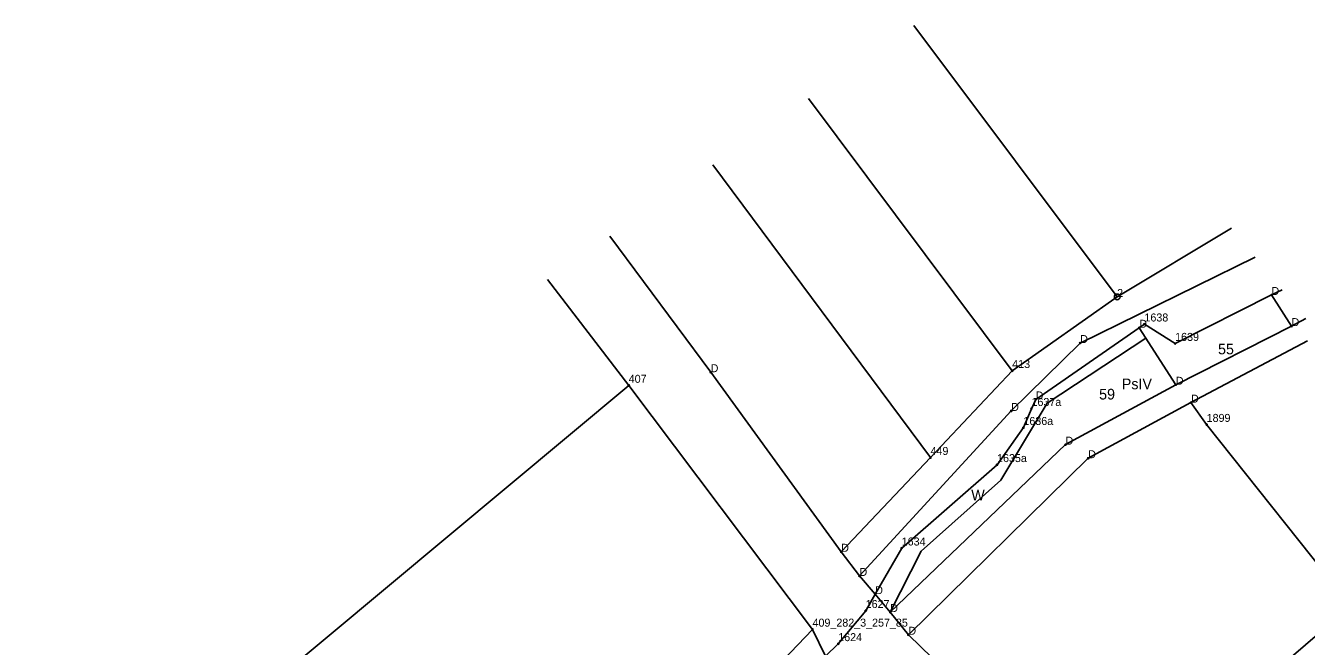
# Model space of a CAD drawing. Extents: x 7467189 to 7469366, y 5491487 to 5492734.
# Drawn here: x 7467205.5 to 7467385.5, y 5492646.7 to 5492734 of the extents above; entities that cross this region are included whole.
import ezdxf

# ---------------------------------------------------------------- set-up
doc = ezdxf.new("R2010")
doc.units = 0
for name, color, linetype in [('202-punkt graniczny', 7, 'Continuous'), ('202-punkt graniczny-Atr103', 7, 'Continuous'), ('203-punkt graniczny', 7, 'Continuous'), ('203-punkt graniczny-Atr103', 7, 'Continuous'), ('209-oznaczenie konturu klasyfikacyjnego', 7, 'Continuous'), ('210-oznaczenie konturu użytku gruntowego', 7, 'Continuous'), ('211-numer działki ewidencyjnej', 7, 'Continuous'), ('217-kontur klasyfikacyjny', 7, 'Continuous'), ('218-kontur użytku gruntowego', 7, 'Continuous'), ('219-działka ewidencyjna', 7, 'Continuous')]:
    doc.layers.add(name, color=color, linetype=linetype)

# ---------------------------------------------------------------- blocks, each defined once
blk = doc.blocks.new('203')
blk.add_circle((0, 0), 0.09)
blk = doc.blocks.new('202')
blk.add_circle((0, 0), 0.4)

msp = doc.modelspace()

# ---------------------------------------------------------------- linework, layer by layer
at = {"layer": '217-kontur klasyfikacyjny'}
for points in [[(7467358.92, 5492695.86), (7467374.98, 5492705.51)], [(7467287.64, 5492704.41), (7467301.8, 5492685.28)], [(7467290.28, 5492683.42), (7467278.88, 5492698.33)], [(7467344.17, 5492685.49), (7467358.92, 5492695.86)], [(7467380.6, 5492696.14), (7467367.07, 5492689.31)], [(7467383.43, 5492691.76), (7467380.6, 5492696.14)], [(7467362.75, 5492692.03), (7467362.03, 5492691.53)], [(7467362.03, 5492691.53), (7467362.95, 5492690.08)], [(7467367.07, 5492689.31), (7467362.75, 5492692.03)], [(7467367.16, 5492683.51), (7467383.43, 5492691.76)], [(7467362.95, 5492690.08), (7467349.1, 5492680.93)], [(7467385.67, 5492689.68), (7467369.29, 5492681)], [(7467332.69, 5492673.27), (7467344.17, 5492685.49)], [(7467301.8, 5492685.28), (7467320.14, 5492660.03)], [(7467316.11, 5492649.12), (7467290.28, 5492683.42)], [(7467351.66, 5492675.09), (7467367.16, 5492683.51)], [(7467349.1, 5492680.93), (7467342.58, 5492670.08)], [(7467369.29, 5492681), (7467354.84, 5492673.18)], [(7467327.03, 5492651.55), (7467351.66, 5492675.09)], [(7467320.14, 5492660.03), (7467332.69, 5492673.27)], [(7467354.84, 5492673.18), (7467329.58, 5492648.36)], [(7467342.58, 5492670.08), (7467331.38, 5492660.13)], [(7467331.38, 5492660.13), (7467327.03, 5492651.55)], [(7467294.41, 5492626.43), (7467316.11, 5492649.12)], [(7467329.58, 5492648.36), (7467374.17, 5492604.99)]]:
    msp.add_lwpolyline(points, dxfattribs=at)
at = {"layer": '218-kontur użytku gruntowego'}
for points in [[(7467358.92, 5492695.86), (7467374.98, 5492705.51)], [(7467287.64, 5492704.41), (7467301.8, 5492685.28)], [(7467378.33, 5492701.44), (7467353.72, 5492689.38)], [(7467290.28, 5492683.42), (7467278.88, 5492698.33)], [(7467382.12, 5492696.86), (7467380.6, 5492696.14)], [(7467344.17, 5492685.49), (7467358.92, 5492695.86)], [(7467380.6, 5492696.14), (7467367.07, 5492689.31)], [(7467383.43, 5492691.76), (7467380.6, 5492696.14)], [(7467383.43, 5492691.76), (7467385.43, 5492692.85)], [(7467362.03, 5492691.53), (7467347.47, 5492681.45)], [(7467362.75, 5492692.03), (7467362.03, 5492691.53)], [(7467362.95, 5492690.08), (7467362.03, 5492691.53)], [(7467367.07, 5492689.31), (7467362.75, 5492692.03)], [(7467367.16, 5492683.51), (7467383.43, 5492691.76)], [(7467353.72, 5492689.38), (7467344.03, 5492679.83)], [(7467349.1, 5492680.93), (7467362.95, 5492690.08)], [(7467385.67, 5492689.68), (7467369.29, 5492681)], [(7467332.69, 5492673.27), (7467344.17, 5492685.49)], [(7467301.8, 5492685.28), (7467320.14, 5492660.03)], [(7467316.11, 5492649.12), (7467290.28, 5492683.42)], [(7467351.66, 5492675.09), (7467367.16, 5492683.51)], [(7467342.58, 5492670.08), (7467349.1, 5492680.93)], [(7467346.88, 5492680.15), (7467345.74, 5492677.48)], [(7467347.47, 5492681.45), (7467346.88, 5492680.15)], [(7467369.29, 5492681), (7467354.84, 5492673.18)], [(7467344.03, 5492679.83), (7467322.71, 5492656.63)], [(7467345.74, 5492677.48), (7467342.04, 5492672.27)], [(7467327.03, 5492651.55), (7467351.66, 5492675.09)], [(7467320.14, 5492660.03), (7467332.69, 5492673.27)], [(7467354.84, 5492673.18), (7467329.58, 5492648.36)], [(7467342.04, 5492672.27), (7467328.64, 5492660.53)], [(7467331.38, 5492660.13), (7467342.58, 5492670.08)], [(7467328.64, 5492660.53), (7467324.92, 5492654.07)], [(7467327.03, 5492651.55), (7467331.38, 5492660.13)], [(7467322.71, 5492656.63), (7467324.92, 5492654.07)], [(7467323.58, 5492651.74), (7467324.92, 5492654.07)], [(7467324.92, 5492654.07), (7467327.03, 5492651.55)], [(7467319.72, 5492647.08), (7467323.58, 5492651.74)], [(7467294.41, 5492626.43), (7467316.11, 5492649.12)], [(7467329.58, 5492648.36), (7467374.17, 5492604.99)], [(7467317.91, 5492645.33), (7467319.72, 5492647.08)]]:
    msp.add_lwpolyline(points, dxfattribs=at)
at = {"layer": '219-działka ewidencyjna'}
for points in [[(7467330.33, 5492734.02), (7467358.92, 5492695.86)], [(7467315.52, 5492723.75), (7467344.17, 5492685.49)], [(7467302.12, 5492714.45), (7467332.69, 5492673.27)], [(7467358.92, 5492695.86), (7467374.98, 5492705.51)], [(7467287.64, 5492704.41), (7467301.8, 5492685.28)], [(7467353.72, 5492689.38), (7467378.33, 5492701.44)], [(7467278.88, 5492698.33), (7467290.28, 5492683.42)], [(7467380.6, 5492696.14), (7467382.12, 5492696.86)], [(7467358.92, 5492695.86), (7467344.17, 5492685.49)], [(7467380.6, 5492696.14), (7467367.07, 5492689.31)], [(7467383.43, 5492691.76), (7467380.6, 5492696.14)], [(7467383.43, 5492691.76), (7467385.43, 5492692.85)], [(7467347.47, 5492681.45), (7467362.03, 5492691.53)], [(7467362.03, 5492691.53), (7467362.75, 5492692.03)], [(7467367.16, 5492683.51), (7467362.03, 5492691.53)], [(7467362.75, 5492692.03), (7467367.07, 5492689.31)], [(7467367.16, 5492683.51), (7467383.43, 5492691.76)], [(7467344.03, 5492679.83), (7467353.72, 5492689.38)], [(7467369.29, 5492681), (7467385.67, 5492689.68)], [(7467332.69, 5492673.27), (7467344.17, 5492685.49)], [(7467301.8, 5492685.28), (7467320.14, 5492660.03)], [(7467205.53, 5492612.63), (7467290.28, 5492683.42)], [(7467290.28, 5492683.42), (7467316.11, 5492649.12)], [(7467351.66, 5492675.09), (7467367.16, 5492683.51)], [(7467345.74, 5492677.48), (7467346.88, 5492680.15)], [(7467347.47, 5492681.45), (7467346.88, 5492680.15)], [(7467354.84, 5492673.18), (7467369.29, 5492681)], [(7467369.29, 5492681), (7467371.49, 5492677.91)], [(7467322.71, 5492656.63), (7467344.03, 5492679.83)], [(7467342.04, 5492672.27), (7467345.74, 5492677.48)], [(7467371.49, 5492677.91), (7467391.77, 5492652.42)], [(7467327.03, 5492651.55), (7467351.66, 5492675.09)], [(7467320.14, 5492660.03), (7467332.69, 5492673.27)], [(7467329.58, 5492648.36), (7467354.84, 5492673.18)], [(7467328.64, 5492660.53), (7467342.04, 5492672.27)], [(7467324.92, 5492654.07), (7467328.64, 5492660.53)], [(7467320.14, 5492660.03), (7467322.71, 5492656.63)], [(7467324.92, 5492654.07), (7467322.71, 5492656.63)], [(7467324.92, 5492654.07), (7467323.58, 5492651.74)], [(7467324.92, 5492654.07), (7467327.03, 5492651.55)], [(7467319.72, 5492647.08), (7467323.58, 5492651.74)], [(7467327.03, 5492651.55), (7467329.58, 5492648.36)], [(7467374.99, 5492637.99), (7467391.77, 5492652.42)], [(7467294.41, 5492626.43), (7467316.11, 5492649.12)], [(7467317.91, 5492645.33), (7467316.11, 5492649.12)], [(7467329.58, 5492648.36), (7467374.17, 5492604.99)], [(7467317.91, 5492645.33), (7467319.72, 5492647.08)]]:
    msp.add_lwpolyline(points, dxfattribs=at)

# ---------------------------------------------------------------- block references
at = {"layer": '202-punkt graniczny'}
msp.add_blockref('202', (7467358.92, 5492695.86), dxfattribs=at)
at = {"layer": '203-punkt graniczny'}
for p in [(7467380.6, 5492696.14), (7467362.03, 5492691.53), (7467362.75, 5492692.03), (7467383.43, 5492691.76), (7467353.72, 5492689.38), (7467367.07, 5492689.31), (7467301.8, 5492685.28), (7467344.17, 5492685.49), (7467367.16, 5492683.51), (7467290.28, 5492683.42), (7467346.88, 5492680.15), (7467347.47, 5492681.45), (7467369.29, 5492681), (7467344.03, 5492679.83), (7467345.74, 5492677.48), (7467371.49, 5492677.91), (7467351.66, 5492675.09), (7467332.69, 5492673.27), (7467354.84, 5492673.18), (7467342.04, 5492672.27), (7467328.64, 5492660.53), (7467320.14, 5492660.03), (7467322.71, 5492656.63), (7467324.92, 5492654.07), (7467323.58, 5492651.74), (7467327.03, 5492651.55), (7467316.11, 5492649.12), (7467329.58, 5492648.36), (7467319.72, 5492647.08)]:
    msp.add_blockref('203', p, dxfattribs=at)

# ---------------------------------------------------------------- texts
at = {"layer": '202-punkt graniczny-Atr103'}
msp.add_text('2', height=1.12, dxfattribs=at).set_placement((7467358.92, 5492695.86))
at = {"layer": '203-punkt graniczny-Atr103'}
for s, height, p in [('D', 1.12, (7467380.6, 5492696.14)), ('D', 1.12, (7467362.03, 5492691.53)), ('1638', 1.125, (7467362.75, 5492692.41)), ('D', 1.12, (7467383.43, 5492691.76)), ('1639', 1.125, (7467367.07, 5492689.68)), ('D', 1.12, (7467353.72, 5492689.38)), ('D', 1.12, (7467301.8, 5492685.28)), ('413', 1.125, (7467344.17, 5492685.87)), ('407', 1.125, (7467290.28, 5492683.79)), ('D', 1.12, (7467367.16, 5492683.51)), ('D', 1.12, (7467347.47, 5492681.45)), ('D', 1.12, (7467369.29, 5492681)), ('D', 1.12, (7467344.03, 5492679.83)), ('1637a', 1.125, (7467346.88, 5492680.53)), ('1636a', 1.125, (7467345.74, 5492677.86)), ('1899', 1.125, (7467371.49, 5492678.29)), ('449', 1.125, (7467332.69, 5492673.64)), ('D', 1.12, (7467351.66, 5492675.09)), ('1635a', 1.125, (7467342.04, 5492672.64)), ('D', 1.12, (7467354.84, 5492673.18)), ('1634', 1.125, (7467328.64, 5492660.91)), ('D', 1.12, (7467320.14, 5492660.03)), ('D', 1.12, (7467322.71, 5492656.63)), ('D', 1.12, (7467324.92, 5492654.07)), ('1627', 1.125, (7467323.58, 5492652.12)), ('D', 1.12, (7467327.03, 5492651.55)), ('409_282_3_257_85', 1.125, (7467316.11, 5492649.5)), ('D', 1.12, (7467329.58, 5492648.36)), ('1624', 1.125, (7467319.72, 5492647.46))]:
    msp.add_text(s, height=height, dxfattribs=at).set_placement(p)
at = {"layer": '209-oznaczenie konturu klasyfikacyjnego'}
msp.add_text('PsIV', height=1.5, dxfattribs=at).set_placement((7467359.57, 5492682.88))
at = {"layer": '210-oznaczenie konturu użytku gruntowego'}
for s, p in [('Ps', (7467359.57, 5492682.88)), ('W', (7467338.41, 5492667.24))]:
    msp.add_text(s, height=1.5, dxfattribs=at).set_placement(p)
at = {"layer": '211-numer działki ewidencyjnej'}
for s, p in [('55', (7467373.09, 5492687.79)), ('59', (7467356.38, 5492681.44))]:
    msp.add_text(s, height=1.5, dxfattribs=at).set_placement(p)

doc.saveas('drawing.dxf')
